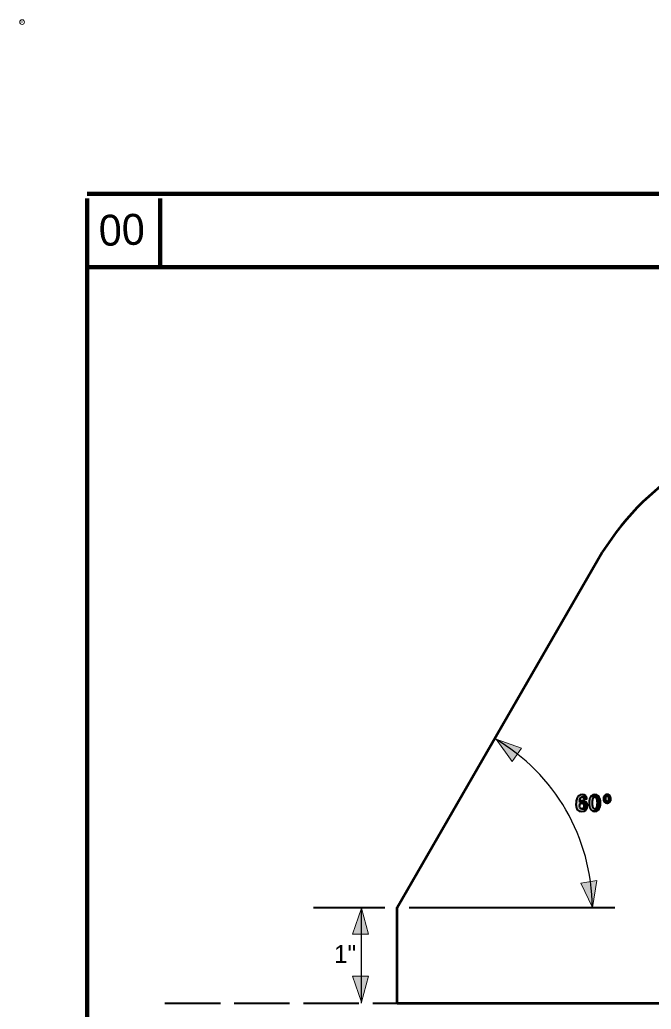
# Model space of a CAD drawing. Extents: x -9575 to -7980, y -62851 to -56618.
# Drawn here: x -9575 to -9090, y -62416 to -61655 of the extents above; entities that cross this region are included whole.
import ezdxf

# ---------------------------------------------------------------- set-up
doc = ezdxf.new("R2010")
doc.units = 0
doc.header["$LTSCALE"] = 7.1
doc.header["$PDMODE"] = 32
doc.header["$PDSIZE"] = 3.55
doc.linetypes.add('LONG_DASHED', pattern=[7.5, 6, -1.5])
doc.layers.add('1', color=7, linetype='Continuous', lineweight=13)
doc.layers.add('3', color=7, linetype='Continuous', lineweight=40)

msp = doc.modelspace()

# ---------------------------------------------------------------- hatches: boundary and pattern name
at = {"layer": '1'}
for points in [[(-9208.9, -62208.3), (-9196.54, -62225.48), (-9189.34, -62215.26)], [(-9134.94, -62337.88), (-9131.54, -62317), (-9143.86, -62319.12)], [(-9312.6, -62338.3), (-9319.5, -62358.3), (-9307, -62358.3)], [(-9312.6, -62410.8), (-9319.5, -62390.8), (-9307, -62390.8)]]:
    msp.add_hatch(color=256, dxfattribs=at).paths.add_polyline_path(points)
at = {"layer": '3'}
for points in [[(-9144.42, -62263.76), (-9143.3, -62264.02), (-9141.48, -62263.76), (-9141.24, -62263.62), (-9140, -62262.9), (-9139.86, -62262.66), (-9139.38, -62261.94), (-9143, -62261.94), (-9143.7, -62261.8), (-9143.76, -62261.76), (-9144.26, -62261.34), (-9144.26, -62261.34), (-9144.3, -62261.24), (-9144.62, -62260.6), (-9144.72, -62259.72), (-9144.7, -62259.52), (-9144.64, -62259.06), (-9144.64, -62259.06), (-9144.62, -62258.84), (-9144.3, -62258.16), (-9144.04, -62257.92), (-9143.78, -62257.72), (-9143.06, -62257.54), (-9139.14, -62257.54), (-9139.66, -62256.68), (-9139.74, -62256.56), (-9139.94, -62256.44), (-9144.68, -62256.44), (-9144.66, -62255.8), (-9144.64, -62255.72), (-9144.6, -62255.04), (-9144.4, -62254.16), (-9144.36, -62253.98), (-9144.34, -62253.88), (-9144.06, -62253.48), (-9143.8, -62253.12), (-9143.4, -62252.94), (-9143.26, -62252.88), (-9143.02, -62252.78), (-9139.4, -62252.78), (-9139.86, -62252.1), (-9140.04, -62251.82), (-9141.22, -62251.14), (-9141.3, -62251.08), (-9142.74, -62250.88), (-9142.74, -62250.88), (-9144, -62251.08), (-9144.34, -62251.14), (-9145.42, -62251.82), (-9145.86, -62252.1), (-9146.26, -62252.78), (-9146.32, -62252.88), (-9146.34, -62252.94), (-9146.46, -62253.12), (-9146.66, -62253.48), (-9146.9, -62253.88), (-9146.96, -62253.98), (-9147, -62254.16), (-9147.18, -62255.04), (-9147.32, -62255.72), (-9147.34, -62255.8), (-9147.46, -62256.44), (-9147.48, -62256.56), (-9147.5, -62256.68), (-9147.52, -62257.54), (-9147.54, -62257.72), (-9147.54, -62257.92), (-9147.54, -62258.16), (-9147.56, -62258.84), (-9147.56, -62259.06), (-9147.48, -62259.52), (-9147.44, -62259.72), (-9147.28, -62260.6), (-9147.18, -62261.24), (-9147.12, -62261.34), (-9147.12, -62261.34), (-9146.88, -62261.76), (-9146.86, -62261.8), (-9146.78, -62261.94), (-9146.38, -62262.66), (-9146.06, -62262.9), (-9145.04, -62263.62)], [(-9143.74, -62255.8), (-9144.68, -62256.44), (-9139.94, -62256.44), (-9140.98, -62255.8), (-9141.06, -62255.72), (-9142.42, -62255.5), (-9142.42, -62255.5), (-9143.46, -62255.72)], [(-9141.54, -62253.98), (-9141.5, -62254.16), (-9139.14, -62254.16), (-9139.16, -62253.98), (-9139.18, -62253.88), (-9139.24, -62253.48), (-9139.3, -62253.12), (-9139.34, -62252.94), (-9139.34, -62252.88), (-9139.4, -62252.78), (-9143.02, -62252.78), (-9142.52, -62252.88), (-9142.22, -62252.94), (-9142.06, -62253.12), (-9141.68, -62253.48), (-9141.58, -62253.88)], [(-9136.18, -62262.62), (-9134.68, -62263.72), (-9131.46, -62263.72), (-9129.96, -62262.62), (-9129.72, -62262.08), (-9133.06, -62262.08), (-9133.68, -62261.9), (-9134.18, -62261.3), (-9134.46, -62260.46), (-9134.56, -62260.16), (-9134.74, -62258.84), (-9134.78, -62257.44), (-9134.74, -62256.02), (-9134.56, -62254.72), (-9134.46, -62254.4), (-9134.18, -62253.56), (-9133.68, -62252.96), (-9133.06, -62252.78), (-9129.72, -62252.78), (-9129.96, -62252.24), (-9136.18, -62252.24), (-9136.42, -62252.78), (-9136.5, -62252.96), (-9136.78, -62253.56), (-9137.16, -62254.4), (-9137.2, -62254.72), (-9137.34, -62256.02), (-9137.5, -62257.44), (-9137.34, -62258.84), (-9137.2, -62260.16), (-9137.16, -62260.46), (-9136.78, -62261.3), (-9136.5, -62261.9), (-9136.42, -62262.08)], [(-9134.68, -62251.14), (-9136.18, -62252.24), (-9129.96, -62252.24), (-9131.46, -62251.14), (-9133.06, -62250.88)], [(-9132.44, -62261.9), (-9133.06, -62262.08), (-9129.72, -62262.08), (-9129.64, -62261.9), (-9129.36, -62261.3), (-9128.98, -62260.46), (-9128.94, -62260.16), (-9128.78, -62258.84), (-9128.62, -62257.44), (-9128.78, -62256.02), (-9128.94, -62254.72), (-9128.98, -62254.4), (-9129.36, -62253.56), (-9129.64, -62252.96), (-9129.72, -62252.78), (-9133.06, -62252.78), (-9132.44, -62252.96), (-9131.94, -62253.56), (-9131.66, -62254.4), (-9131.58, -62254.72), (-9131.38, -62256.02), (-9131.34, -62257.44), (-9131.38, -62258.84), (-9131.58, -62260.16), (-9131.66, -62260.46), (-9131.94, -62261.3)], [(-9126.3, -62255.44), (-9126.28, -62255.56), (-9124.42, -62255.56), (-9124.46, -62255.44), (-9124.58, -62255.02), (-9124.58, -62254.94), (-9124.64, -62254.24), (-9124.64, -62254.22), (-9124.64, -62254.12), (-9124.62, -62254.08), (-9124.58, -62253.4), (-9124.54, -62253.28), (-9124.42, -62252.88), (-9124.36, -62252.72), (-9124.34, -62252.68), (-9124.34, -62252.68), (-9124.32, -62252.66), (-9124, -62252.3), (-9123.92, -62252.28), (-9123.58, -62252.2), (-9121.2, -62252.2), (-9121.46, -62251.72), (-9121.5, -62251.64), (-9122.42, -62251.06), (-9122.48, -62251.02), (-9123.58, -62250.88), (-9124.52, -62251.02), (-9124.72, -62251.06), (-9125.56, -62251.64), (-9125.7, -62251.72), (-9125.94, -62252.2), (-9125.98, -62252.28), (-9125.98, -62252.3), (-9126.18, -62252.66), (-9126.18, -62252.68), (-9126.2, -62252.72), (-9126.28, -62252.88), (-9126.34, -62253.28), (-9126.34, -62253.4), (-9126.42, -62254.08), (-9126.44, -62254.12), (-9126.46, -62254.22), (-9126.46, -62254.24), (-9126.36, -62254.94), (-9126.34, -62255.02)], [(-9125.82, -62256.54), (-9125.74, -62256.66), (-9121.52, -62256.66), (-9121.38, -62256.54), (-9121.24, -62256.22), (-9123.54, -62256.22), (-9124.02, -62256.12), (-9124.06, -62256.06), (-9124.38, -62255.68), (-9124.4, -62255.6), (-9124.42, -62255.56), (-9126.28, -62255.56), (-9126.26, -62255.6), (-9126.22, -62255.68), (-9126.04, -62256.06), (-9126.02, -62256.12), (-9125.96, -62256.22)], [(-9123.7, -62257.52), (-9123.48, -62257.56), (-9123.34, -62257.52), (-9123.2, -62257.48), (-9122.68, -62257.36), (-9122.26, -62257.28), (-9121.52, -62256.66), (-9125.76, -62256.66), (-9124.9, -62257.28), (-9124.78, -62257.36), (-9123.94, -62257.48)], [(-9123.22, -62256.12), (-9123.54, -62256.22), (-9121.24, -62256.22), (-9121.18, -62256.12), (-9121.16, -62256.06), (-9120.98, -62255.68), (-9120.96, -62255.6), (-9120.94, -62255.56), (-9120.86, -62255.44), (-9120.82, -62255.02), (-9120.82, -62254.94), (-9120.72, -62254.24), (-9120.72, -62254.22), (-9120.7, -62254.12), (-9120.7, -62254.08), (-9120.8, -62253.4), (-9120.82, -62253.28), (-9120.88, -62252.88), (-9120.9, -62252.72), (-9120.9, -62252.68), (-9120.94, -62252.66), (-9120.94, -62252.66), (-9121.14, -62252.3), (-9121.14, -62252.3), (-9121.14, -62252.28), (-9121.2, -62252.2), (-9123.58, -62252.2), (-9123.18, -62252.28), (-9123.14, -62252.3), (-9122.82, -62252.66), (-9122.8, -62252.68), (-9122.78, -62252.72), (-9122.74, -62252.88), (-9122.58, -62253.28), (-9122.58, -62253.4), (-9122.52, -62254.08), (-9122.5, -62254.12), (-9122.52, -62254.22), (-9122.52, -62254.24), (-9122.58, -62254.94), (-9122.58, -62255.02), (-9122.7, -62255.44), (-9122.74, -62255.56), (-9122.76, -62255.6), (-9122.82, -62255.68), (-9123.1, -62256.06)], [(-9142.5, -62261.8), (-9143, -62261.94), (-9139.38, -62261.94), (-9139.28, -62261.8), (-9139.26, -62261.76), (-9138.98, -62261.34), (-9138.98, -62261.34), (-9138.96, -62261.24), (-9138.84, -62260.6), (-9138.7, -62259.72), (-9138.66, -62259.52), (-9138.74, -62259.06), (-9138.76, -62258.84), (-9138.86, -62258.16), (-9138.9, -62257.92), (-9139.02, -62257.72), (-9139.14, -62257.54), (-9143.06, -62257.54), (-9142.36, -62257.72), (-9142.1, -62257.92), (-9141.84, -62258.16), (-9141.52, -62258.84), (-9141.5, -62259.06), (-9141.44, -62259.52), (-9141.42, -62259.72), (-9141.52, -62260.6), (-9141.82, -62261.24), (-9141.86, -62261.34), (-9141.86, -62261.34), (-9142.36, -62261.76)], [(-9134.68, -62263.72), (-9133.06, -62264), (-9131.46, -62263.72)]]:
    msp.add_hatch(color=256, dxfattribs=at).paths.add_polyline_path(points)

# ---------------------------------------------------------------- linework, layer by layer
at = {"layer": '1', "lineweight": 100}
for p, q in [((-8031.28, -61788.8), (-9523.5, -61788.8)), ((-9467.26, -61792.3), (-9467.26, -61845.06)), ((-8031.28, -61845.06), (-9523.5, -61845.06))]:
    msp.add_line(p, q, dxfattribs=at)
msp.add_lwpolyline([(-9523.5, -61792.3), (-9523.5, -62810.24), (-8032.74, -62810.24)], dxfattribs=at)
at = {"layer": '1'}
for points in [[(-9208.9, -62208.3), (-9196.54, -62225.48), (-9189.34, -62215.26)], [(-9134.94, -62337.88), (-9131.54, -62317), (-9143.86, -62319.12)], [(-9312.6, -62338.3), (-9319.5, -62358.3), (-9307, -62358.3)], [(-9312.6, -62410.8), (-9319.5, -62390.8), (-9307, -62390.8)]]:
    msp.add_lwpolyline(points, close=True, dxfattribs=at)
msp.add_point((-9573.46, -61656.6), dxfattribs=at)
at = {"layer": '3'}
for p, q in [((-9349.34, -62337.8), (-9294.42, -62337.8)), ((-9275.82, -62337.8), (-9117.74, -62337.8))]:
    msp.add_line(p, q, dxfattribs=at)
at = {"layer": '3', "lineweight": 25}
msp.add_line((-9312.44, -62411.44), (-9312.44, -62337.8), dxfattribs=at)
at = {"layer": '3', "linetype": 'LONG_DASHED'}
msp.add_line((-9463.62, -62411.44), (-9285.14, -62411.44), dxfattribs=at)
at = {"layer": '3', "lineweight": 53}
msp.add_line((-9285.14, -62411.44), (-8683.18, -62411.44), dxfattribs=at)
msp.add_lwpolyline([(-9285.14, -62411.44), (-9285.14, -62337.8), (-9127.34, -62064.5)], dxfattribs=at)
at = {"layer": '3'}
for points in [[(-9144.42, -62263.76), (-9143.3, -62264.02), (-9141.48, -62263.76), (-9141.24, -62263.62), (-9140, -62262.9), (-9139.86, -62262.66), (-9139.38, -62261.94), (-9143, -62261.94), (-9143.7, -62261.8), (-9143.76, -62261.76), (-9144.26, -62261.34), (-9144.26, -62261.34), (-9144.3, -62261.24), (-9144.62, -62260.6), (-9144.72, -62259.72), (-9144.7, -62259.52), (-9144.64, -62259.06), (-9144.64, -62259.06), (-9144.62, -62258.84), (-9144.3, -62258.16), (-9144.04, -62257.92), (-9143.78, -62257.72), (-9143.06, -62257.54), (-9139.14, -62257.54), (-9139.66, -62256.68), (-9139.74, -62256.56), (-9139.94, -62256.44), (-9144.68, -62256.44), (-9144.66, -62255.8), (-9144.64, -62255.72), (-9144.6, -62255.04), (-9144.4, -62254.16), (-9144.36, -62253.98), (-9144.34, -62253.88), (-9144.06, -62253.48), (-9143.8, -62253.12), (-9143.4, -62252.94), (-9143.26, -62252.88), (-9143.02, -62252.78), (-9139.4, -62252.78), (-9139.86, -62252.1), (-9140.04, -62251.82), (-9141.22, -62251.14), (-9141.3, -62251.08), (-9142.74, -62250.88), (-9142.74, -62250.88), (-9144, -62251.08), (-9144.34, -62251.14), (-9145.42, -62251.82), (-9145.86, -62252.1), (-9146.26, -62252.78), (-9146.32, -62252.88), (-9146.34, -62252.94), (-9146.46, -62253.12), (-9146.66, -62253.48), (-9146.9, -62253.88), (-9146.96, -62253.98), (-9147, -62254.16), (-9147.18, -62255.04), (-9147.32, -62255.72), (-9147.34, -62255.8), (-9147.46, -62256.44), (-9147.48, -62256.56), (-9147.5, -62256.68), (-9147.52, -62257.54), (-9147.54, -62257.72), (-9147.54, -62257.92), (-9147.54, -62258.16), (-9147.56, -62258.84), (-9147.56, -62259.06), (-9147.48, -62259.52), (-9147.44, -62259.72), (-9147.28, -62260.6), (-9147.18, -62261.24), (-9147.12, -62261.34), (-9147.12, -62261.34), (-9146.88, -62261.76), (-9146.86, -62261.8), (-9146.78, -62261.94), (-9146.38, -62262.66), (-9146.06, -62262.9), (-9145.04, -62263.62)], [(-9143.74, -62255.8), (-9144.68, -62256.44), (-9139.94, -62256.44), (-9140.98, -62255.8), (-9141.06, -62255.72), (-9142.42, -62255.5), (-9142.42, -62255.5), (-9143.46, -62255.72)], [(-9141.54, -62253.98), (-9141.5, -62254.16), (-9139.14, -62254.16), (-9139.16, -62253.98), (-9139.18, -62253.88), (-9139.24, -62253.48), (-9139.3, -62253.12), (-9139.34, -62252.94), (-9139.34, -62252.88), (-9139.4, -62252.78), (-9143.02, -62252.78), (-9142.52, -62252.88), (-9142.22, -62252.94), (-9142.06, -62253.12), (-9141.68, -62253.48), (-9141.58, -62253.88)], [(-9136.18, -62262.62), (-9134.68, -62263.72), (-9131.46, -62263.72), (-9129.96, -62262.62), (-9129.72, -62262.08), (-9133.06, -62262.08), (-9133.68, -62261.9), (-9134.18, -62261.3), (-9134.46, -62260.46), (-9134.56, -62260.16), (-9134.74, -62258.84), (-9134.78, -62257.44), (-9134.74, -62256.02), (-9134.56, -62254.72), (-9134.46, -62254.4), (-9134.18, -62253.56), (-9133.68, -62252.96), (-9133.06, -62252.78), (-9129.72, -62252.78), (-9129.96, -62252.24), (-9136.18, -62252.24), (-9136.42, -62252.78), (-9136.5, -62252.96), (-9136.78, -62253.56), (-9137.16, -62254.4), (-9137.2, -62254.72), (-9137.34, -62256.02), (-9137.5, -62257.44), (-9137.34, -62258.84), (-9137.2, -62260.16), (-9137.16, -62260.46), (-9136.78, -62261.3), (-9136.5, -62261.9), (-9136.42, -62262.08)], [(-9134.68, -62251.14), (-9136.18, -62252.24), (-9129.96, -62252.24), (-9131.46, -62251.14), (-9133.06, -62250.88)], [(-9132.44, -62261.9), (-9133.06, -62262.08), (-9129.72, -62262.08), (-9129.64, -62261.9), (-9129.36, -62261.3), (-9128.98, -62260.46), (-9128.94, -62260.16), (-9128.78, -62258.84), (-9128.62, -62257.44), (-9128.78, -62256.02), (-9128.94, -62254.72), (-9128.98, -62254.4), (-9129.36, -62253.56), (-9129.64, -62252.96), (-9129.72, -62252.78), (-9133.06, -62252.78), (-9132.44, -62252.96), (-9131.94, -62253.56), (-9131.66, -62254.4), (-9131.58, -62254.72), (-9131.38, -62256.02), (-9131.34, -62257.44), (-9131.38, -62258.84), (-9131.58, -62260.16), (-9131.66, -62260.46), (-9131.94, -62261.3)], [(-9126.3, -62255.44), (-9126.28, -62255.56), (-9124.42, -62255.56), (-9124.46, -62255.44), (-9124.58, -62255.02), (-9124.58, -62254.94), (-9124.64, -62254.24), (-9124.64, -62254.22), (-9124.64, -62254.12), (-9124.62, -62254.08), (-9124.58, -62253.4), (-9124.54, -62253.28), (-9124.42, -62252.88), (-9124.36, -62252.72), (-9124.34, -62252.68), (-9124.34, -62252.68), (-9124.32, -62252.66), (-9124, -62252.3), (-9123.92, -62252.28), (-9123.58, -62252.2), (-9121.2, -62252.2), (-9121.46, -62251.72), (-9121.5, -62251.64), (-9122.42, -62251.06), (-9122.48, -62251.02), (-9123.58, -62250.88), (-9124.52, -62251.02), (-9124.72, -62251.06), (-9125.56, -62251.64), (-9125.7, -62251.72), (-9125.94, -62252.2), (-9125.98, -62252.28), (-9125.98, -62252.3), (-9126.18, -62252.66), (-9126.18, -62252.68), (-9126.2, -62252.72), (-9126.28, -62252.88), (-9126.34, -62253.28), (-9126.34, -62253.4), (-9126.42, -62254.08), (-9126.44, -62254.12), (-9126.46, -62254.22), (-9126.46, -62254.24), (-9126.36, -62254.94), (-9126.34, -62255.02)], [(-9125.82, -62256.54), (-9125.74, -62256.66), (-9121.52, -62256.66), (-9121.38, -62256.54), (-9121.24, -62256.22), (-9123.54, -62256.22), (-9124.02, -62256.12), (-9124.06, -62256.06), (-9124.38, -62255.68), (-9124.4, -62255.6), (-9124.42, -62255.56), (-9126.28, -62255.56), (-9126.26, -62255.6), (-9126.22, -62255.68), (-9126.04, -62256.06), (-9126.02, -62256.12), (-9125.96, -62256.22)], [(-9123.7, -62257.52), (-9123.48, -62257.56), (-9123.34, -62257.52), (-9123.2, -62257.48), (-9122.68, -62257.36), (-9122.26, -62257.28), (-9121.52, -62256.66), (-9125.76, -62256.66), (-9124.9, -62257.28), (-9124.78, -62257.36), (-9123.94, -62257.48)], [(-9123.22, -62256.12), (-9123.54, -62256.22), (-9121.24, -62256.22), (-9121.18, -62256.12), (-9121.16, -62256.06), (-9120.98, -62255.68), (-9120.96, -62255.6), (-9120.94, -62255.56), (-9120.86, -62255.44), (-9120.82, -62255.02), (-9120.82, -62254.94), (-9120.72, -62254.24), (-9120.72, -62254.22), (-9120.7, -62254.12), (-9120.7, -62254.08), (-9120.8, -62253.4), (-9120.82, -62253.28), (-9120.88, -62252.88), (-9120.9, -62252.72), (-9120.9, -62252.68), (-9120.94, -62252.66), (-9120.94, -62252.66), (-9121.14, -62252.3), (-9121.14, -62252.3), (-9121.14, -62252.28), (-9121.2, -62252.2), (-9123.58, -62252.2), (-9123.18, -62252.28), (-9123.14, -62252.3), (-9122.82, -62252.66), (-9122.8, -62252.68), (-9122.78, -62252.72), (-9122.74, -62252.88), (-9122.58, -62253.28), (-9122.58, -62253.4), (-9122.52, -62254.08), (-9122.5, -62254.12), (-9122.52, -62254.22), (-9122.52, -62254.24), (-9122.58, -62254.94), (-9122.58, -62255.02), (-9122.7, -62255.44), (-9122.74, -62255.56), (-9122.76, -62255.6), (-9122.82, -62255.68), (-9123.1, -62256.06)], [(-9142.5, -62261.8), (-9143, -62261.94), (-9139.38, -62261.94), (-9139.28, -62261.8), (-9139.26, -62261.76), (-9138.98, -62261.34), (-9138.98, -62261.34), (-9138.96, -62261.24), (-9138.84, -62260.6), (-9138.7, -62259.72), (-9138.66, -62259.52), (-9138.74, -62259.06), (-9138.76, -62258.84), (-9138.86, -62258.16), (-9138.9, -62257.92), (-9139.02, -62257.72), (-9139.14, -62257.54), (-9143.06, -62257.54), (-9142.36, -62257.72), (-9142.1, -62257.92), (-9141.84, -62258.16), (-9141.52, -62258.84), (-9141.5, -62259.06), (-9141.44, -62259.52), (-9141.42, -62259.72), (-9141.52, -62260.6), (-9141.82, -62261.24), (-9141.86, -62261.34), (-9141.86, -62261.34), (-9142.36, -62261.76)], [(-9134.68, -62263.72), (-9133.06, -62264), (-9131.46, -62263.72)]]:
    msp.add_lwpolyline(points, close=True, dxfattribs=at)
at = {"layer": '3', "lineweight": 53}
msp.add_arc((-8948.76, -62176.88), 210.98, 93.97195, 147.8167, dxfattribs=at)
at = {"layer": '3', "lineweight": 25}
msp.add_arc((-9285.13, -62337.8), 150, 0, 59.9984, dxfattribs=at)

# ---------------------------------------------------------------- texts
at = {"layer": '1'}
msp.add_text('00', height=23.78, rotation=2.121, dxfattribs=at).set_placement((-9514.06, -61828.94))
at = {"layer": '3'}
msp.add_text('1" ', height=13.95, dxfattribs=at).set_placement((-9333.58, -62380.56))

doc.saveas('drawing.dxf')
